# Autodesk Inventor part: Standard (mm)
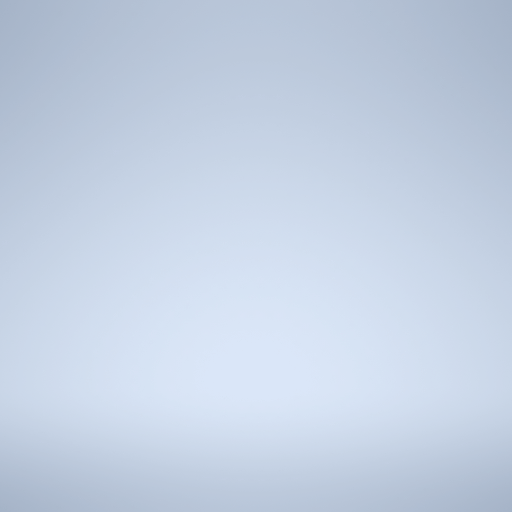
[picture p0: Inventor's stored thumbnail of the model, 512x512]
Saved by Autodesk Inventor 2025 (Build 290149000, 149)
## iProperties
Shininess: 64.0
Length Units: 11269
Angle Units: 11279
Time Units: 11290
Mass Units: 11283
Length Display Precision: 3
Angle Display Precision: 2
Compacted: True
Part Number: Standard (mm)
Document SubType Name: Modeling
Created: 2002-07
Density: 1 g/cm^3
Material: Všeobecné
Appearance: Výchozí
Density: 0.0
Volumn: 0.0
Area: 0.0
PropertySet Name: Model Information
Control State: 0
Master: False
Checked Out: False
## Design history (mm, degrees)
